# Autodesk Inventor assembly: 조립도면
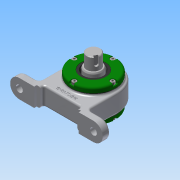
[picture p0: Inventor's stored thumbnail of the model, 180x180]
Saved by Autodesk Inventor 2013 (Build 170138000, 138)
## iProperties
Created: 2019-05
Part Number: 조립도면
Document SubType Name: Assembly
Designer: Administrator
Author: Administrator
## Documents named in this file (13)
- C:\Users\Administrator\Desktop\490504V1050\조립완성품.iam
- C:\Users\Administrator\Desktop\490504V1050\본체.ipt
- C:\Users\Administrator\Desktop\490504V1050\490504V1050\개스킷.ipt
- C:\Users\Administrator\Desktop\490504V1050\490504V1050\그리스니플 M6.ipt
- 그리스니플  M6.ipt
- C:\Users\Administrator\Desktop\490504V1050\490504V1050\그리스니플개스킷.ipt
- C:\Users\Administrator\Desktop\490504V1050\490504V1050\베어링너트.ipt
- C:\Users\Administrator\Desktop\490504V1050\490504V1050\볼트 M4.ipt
- C:\Users\Administrator\Desktop\490504V1050\490504V1050\앵귤러 볼 베어링 7205.ipt
- C:\Users\Administrator\Desktop\490504V1050\490504V1050\오일 실 28 40 5 B.ipt
- C:\Users\Administrator\Desktop\490504V1050\490504V1050\축.ipt
- C:\Users\Administrator\Desktop\490504V1050\490504V1050\칼라.ipt
- C:\Users\Administrator\Desktop\490504V1050\490504V1050\커버.ipt
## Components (4 placed, 3 different names)
1. 개스킷:1
2. 그리스니플  M6:1 — 각도:2
3. 그리스니플개스킷:1
4. 개스킷:2
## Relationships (1: Angle 1)
- 각도:2 [Angle]: 그리스니플  M6:1
